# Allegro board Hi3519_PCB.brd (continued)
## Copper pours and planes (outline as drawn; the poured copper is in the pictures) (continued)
3V3 on TOP (solid shape): 78.06,32.58 78.06,30.7 79.28,29.48 79.28,28.56 79.13,28.41 77.63,28.41 77.42,28.62 77.42,32.58 77.48,32.63 78.01,32.63
3V3 on TOP (solid shape): 107.6,26.18 107.6,13.71 107.5,13.6 104.4,13.6 104.17,13.83 104.17,17.79 104.74,18.37 104.74,26.24 104.93,26.43 107.35,26.43
3V3 on TOP (solid shape): 93.27,27.7 93.27,24.3 93.48,24.09 93.48,22.04 93.45,22.01 93.17,22.01 93.12,22.06 93.12,23.81 92.77,24.17 91.37,24.17 91.22,24.32 91.22,27.65 91.45,27.88 93.1,27.88
3V3 on TOP (solid shape): 64.04,77.61 64.04,74.18 63.78,73.93 63.3,73.93 63.28,73.93 63.02,73.67 63.02,72.66 63.02,71.82 63,71.8 62.79,71.8 62.77,71.82 62.77,72.4 62.64,72.53 62.26,72.53 62.13,72.66 62.13,73.04 62.77,73.04 62.77,73.29 62.51,73.29 62.51,73.04 62.13,73.04 62.13,73.55 62.77,73.55 62.77,73.8 62.51,73.8 62.51,73.55 62.13,73.55 62.13,77.61 62.26,77.74 63.91,77.74
3V3 on BOTTOM (solid shape): 65.05,24.14 65.05,18.43 64.8,18.18 62.77,18.18 62.51,18.43 62.51,23.14 63.25,23.14 63.25,24.05 62.51,24.05 62.51,24.14 62.64,24.27 64.93,24.27
3V3 on BOTTOM (solid shape): 66.58,61.1 66.58,59.58 66.32,59.32 64.57,59.32 64.57,59.34 61.47,59.34 61.47,59.32 61.37,59.32 61.24,59.45 61.24,61.23 61.37,61.36 66.32,61.36
3V3 on BOTTOM (solid shape): 125.13,57.16 125.13,53.23 124.87,52.97 122.84,52.97 122.59,53.23 122.59,56.4 123.22,56.4 123.22,56.66 122.97,56.66 122.97,56.4 122.59,56.4 122.59,56.91 123.22,56.91 123.22,57.16 122.97,57.16 122.97,56.91 122.59,56.91 122.59,57.16 122.84,57.42 124.87,57.42
3V3 on BOTTOM (solid shape): 94.52,12.21 94.52,8.65 94.39,8.52 92.99,8.52 92.87,8.65 92.87,10.81 93.5,10.81 93.5,11.06 93.25,11.06 93.25,10.81 92.87,10.81 92.87,11.32 93.5,11.32 93.5,11.57 93.25,11.57 93.25,11.32 92.87,11.32 92.87,12.21 92.99,12.33 94.39,12.33
3V3 on BOTTOM (solid shape): 101.86,29.94 101.86,29.63 101.83,29.61 100.51,29.61 100.23,29.33 100.23,28.34 100.11,28.21 96.68,28.21 96.42,28.46 96.42,28.59 100.11,28.59 100.11,28.84 99.85,28.84 99.85,28.59 99.6,28.59 99.6,28.84 99.34,28.84 99.34,28.59 96.42,28.59 96.42,29.86 96.53,29.96 101.83,29.96
3V3 on BOTTOM (solid shape): 76.36,10.81 79.53,10.81 79.79,10.56 79.79,9.16 79.53,8.9 75.6,8.9 75.47,9.03 75.47,9.16 76.1,9.16 76.1,9.41 75.85,9.41 75.85,9.16 75.47,9.16 75.47,9.67 76.1,9.67 76.1,9.92 75.85,9.92 75.85,9.67 75.47,9.67 75.47,10.94 75.6,11.06 76.1,11.06
3V3 on BOTTOM (solid shape): 128.68,42.81 128.68,41.39 128.86,41.21 129.8,41.21 129.95,41.37 129.95,42.86 130,42.92 130.89,42.92 130.97,42.84 130.97,38.37 130.71,38.11 127.79,38.11 127.41,38.5 127.41,40.4 130.59,40.4 130.59,40.65 130.33,40.65 130.33,40.4 127.41,40.4 127.41,40.91 130.59,40.91 130.59,41.16 130.33,41.16 130.33,40.91 127.41,40.91 127.41,42.81 127.51,42.92 128.58,42.92
3V3 on BOTTOM (solid shape): 78.9,33.03 78.9,31 79.53,30.37 79.53,29.48 79.41,29.35 77.75,29.35 77.5,29.61 79.15,29.61 79.15,29.86 78.9,29.86 78.9,29.61 77.5,29.61 77.37,29.73 77.37,30.11 79.15,30.11 79.15,30.37 78.9,30.37 78.9,30.11 77.37,30.11 77.37,32.27 78.52,32.27 78.52,32.53 78.26,32.53 78.26,32.27 77.37,32.27 77.37,32.78 78.52,32.78 78.52,33.03 78.26,33.03 78.26,32.78 77.37,32.78 77.37,33.03 77.5,33.16 78.77,33.16
3V3 on POWER5 (solid shape): outline of 42251 points within 52.99,8.52 151.41,84.09
3V3 on TOP: 121.95,55.13 121.95,55.64 123.22,55.64 123.25,55.67 123.25,55.92 123.22,55.95 121.95,55.95 121.95,56.45 123.2,56.45 123.25,56.5 123.25,56.71 123.2,56.76 121.95,56.76 121.95,57.24 123.22,57.24 123.25,57.27 123.25,57.52 123.22,57.55 121.98,57.55 121.95,57.57 121.95,58.03 121.98,58.05 124.96,58.05 125.13,57.89 125.13,55.26 125,55.13
3V3 on TOP: 85.88,46.5 84.74,47.64 84.1,47.64 84.1,49.24 84.59,49.72 85.88,49.72 86.01,49.6 86.01,48.22 86.37,47.87 88.07,47.87 88.3,48.1 90.71,48.1 91.22,48.61 91.22,54.5 91.98,55.26 93.38,55.26 93.5,55.13 93.5,53.1 93.25,53.1 93.25,52.97 93.12,52.97 93.12,52.47 93.5,52.47 93.5,51.83 93.12,51.83 93.12,50.56 93.5,50.56 93.5,49.93 92.99,49.93 92.99,47.64 91.85,46.5
3V3 on BOTTOM: 111.28,50.92 111.13,51.07 110.93,51.07 110.67,51.32 109.28,51.32 109.25,51.35 109.25,51.65 109.28,51.68 111.46,51.68 111.82,51.32 113.19,51.32 113.44,51.07 113.44,45.86 113.19,45.61 111.54,45.61 111.28,45.86 ; 2 cut-outs
3V3 on BOTTOM: 121.44,69.86 121.19,69.61 121.19,68.72 121.06,68.59 119.28,68.59 117.68,70.2 117.68,77.15 118.69,78.16 119.63,78.16 119.66,78.12 119.66,77.03 119.69,77 119.66,76.98 119.66,76.72 119.79,76.6 120.55,76.6 120.68,76.47 120.68,75.22 120.45,75 120.43,75 120.03,74.6 120.03,73.31 120.32,73.01 120.32,71.44 120.63,71.13 122.2,71.13 122.26,71.08 122.26,69.92 122.2,69.86 ; 2 cut-outs
3V3 on BOTTOM: 126.52,64.02 126.52,66.44 126.78,66.69 129.7,66.69 129.95,66.44 129.95,59.7 129.76,59.51 128.05,59.51 127.95,59.61 127.95,62.59 ; 2 cut-outs
3V3_C on TOP (solid shape): 45.24,39.89 45.24,36.21 44.99,35.96 42.96,35.96 42.75,36.16 42.75,36.34 44.23,36.34 44.23,36.59 43.97,36.59 43.97,36.34 43.72,36.34 43.72,36.59 43.46,36.59 43.46,36.34 42.75,36.34 42.75,39.87 42.85,39.97 45.17,39.97
3V3_C on BOTTOM (solid shape): 43.83,38.77 43.83,36.07 43.71,35.96 41.43,35.96 41.33,36.06 41.33,36.44 42.63,36.44 42.63,36.74 41.33,36.74 41.33,37.25 42.63,37.25 42.63,37.56 41.33,37.56 41.33,38.04 42.63,38.04 42.63,38.34 41.33,38.34 41.33,38.78 41.43,38.88 43.72,38.88
3V3_C on ART03 (solid shape): outline of 348 points within 18.06,41.54 37.75,73.29
3V3_C on ART04 (solid shape): outline of 1892 points within 18.32,35.45 43.46,44.85
5V0 on TOP (solid shape): 133.24,35.71 133.24,28.83 133.18,28.77 129.55,28.77 129.44,28.87 129.44,29.8 129.44,29.86 129.19,30.11 127.67,30.11 127.54,30.24 127.54,35.83 127.67,35.96 133,35.96
5V0 on TOP: 151.67,45.3 151.54,45.43 148.7,45.43 148.62,45.35 148.62,44.85 148.67,44.8 151.57,44.8 151.67,44.9
5V0 on TOP: 116.92,50.69 115.68,50.69 115.47,50.89 115.47,52.26 115.65,52.44 118.75,52.44 118.78,52.42 118.78,51.98 118.75,51.96 117.48,51.96 117.43,51.91 117.43,51.7 117.48,51.65 118.7,51.65 118.78,51.58 118.78,51.22 118.7,51.15 117.53,51.15 117.52,51.13 117.37,51.13
5V0 on BOTTOM: 151.54,44.85 151.41,44.72 149.13,44.72 148.75,45.1 148.75,46.5 148.24,47 147.35,47 147.1,47.26 147.1,49.04 147.35,49.29 151.41,49.29 151.54,49.16 ; 2 cut-outs
5V0 on BOTTOM: 115.35,53.74 118.65,53.74 118.9,53.48 118.9,48.4 118.65,48.15 115.35,48.15 115.09,48.4 115.09,53.48 ; 4 cut-outs
5V0 on ART04: 151.54,50.18 151.54,43.96 151.29,43.7 134.78,43.7 133.38,42.31 133.38,42.28 133.25,42.15 133.25,33.29 133,33.03 126.52,33.03 126.14,33.42 126.14,42.81 121.82,47.13 116.36,47.13 115.35,48.15 115.35,52.34 116.74,53.74 130.51,53.74 133.37,50.88 139.39,50.88 139.68,50.59 151.14,50.59
5V0_C on TOP (solid shape): 28.61,37.1 28.61,29.83 28.49,29.72 27.02,29.72 26.85,29.89 26.85,37.12 26.95,37.23 28.48,37.23
5V0_C on TOP (solid shape): 26.45,53.35 26.45,47.51 26.32,47.39 25.3,47.39 25.23,47.46 25.23,51.02 24.67,51.58 24.67,53.35 24.8,53.48 26.32,53.48
5V0_C on TOP (solid shape): 47.4,45.1 47.4,41.42 47.27,41.29 44.86,41.29 44.73,41.42 44.73,41.67 46.26,41.67 46.26,41.92 46,41.92 46,41.67 45.75,41.67 45.75,41.92 45.5,41.92 45.5,41.67 44.73,41.67 44.73,45.1 44.86,45.23 47.27,45.23
5V0_C on BOTTOM (solid shape): 47.4,42.76 47.4,41.62 47.29,41.51 46.68,41.51 46.64,41.54 45.19,41.54 45.14,41.59 45.14,42.03 45.17,42.05 46.61,42.05 46.64,42.08 46.64,42.28 46.56,42.36 45.22,42.36 45.14,42.43 45.14,42.76 45.22,42.84 47.33,42.84
5V0_C on POWER5 (solid shape): outline of 2607 points within 25.16,35.63 47.15,51.58
5V_AUDIO on TOP (solid shape): 22.99,60.97 22.99,59.45 23.02,59.43 23.27,59.43 23.3,59.45 23.3,60.97 23.32,61 23.63,61 23.65,60.97 23.65,58.89 22.92,58.89 22.92,56.96 23.65,56.96 23.65,56.66 23.91,56.4 26.19,56.4 26.32,56.28 26.32,54.29 26.19,54.17 24.57,54.17 20.68,54.17 20.48,54.37 20.48,58.78 20.8,59.1 22.41,59.1 22.61,59.3 22.61,60.97 22.64,61 22.97,61
5V_C_AUDIO on TOP (solid shape): 24.24,35.7 26.19,35.7 26.45,35.45 26.45,33.67 26.03,33.25 26.03,29.95 25.79,29.71 22.43,29.71 22.13,30.01 22.13,34.94 21.85,35.22 21.21,35.22 20.93,34.94 20.93,33.47 20.88,33.42 20.63,33.42 20.58,33.47 20.58,35.42 21.24,36.08 21.24,36.34 23.14,36.34 23.14,36.59 22.89,36.59 22.89,36.34 22.64,36.34 22.64,36.59 22.38,36.59 22.38,36.34 22,36.34 22,36.59 21.75,36.59 21.75,36.34 21.24,36.34 21.24,36.84 21.37,36.97 22.97,36.97
5V_USB2.0 on TOP (solid shape): 23.78,48.78 23.78,47.39 22.62,47.39 22.47,47.24 22.47,44.21 22.28,44.02 15.71,44.02 13.72,46.01 21.21,46.01 21.22,45.96 21.23,45.9 21.25,45.85 21.27,45.8 21.31,45.75 21.35,45.71 21.39,45.68 21.44,45.65 21.49,45.63 21.55,45.61 21.61,45.61 21.66,45.61 21.72,45.62 21.77,45.64 21.82,45.66 21.87,45.69 21.91,45.73 21.95,45.77 21.98,45.82 22,45.87 22.02,45.93 22.03,45.99 22.03,46.04 22.02,46.1 22,46.15 21.98,46.21 21.95,46.25 21.91,46.3 21.87,46.34 21.82,46.37 21.77,46.39 21.72,46.41 21.66,46.42 21.61,46.42 21.55,46.42 21.49,46.4 21.44,46.38 21.39,46.35 21.35,46.32 21.31,46.28 21.27,46.23 21.25,46.18 21.23,46.13 21.22,46.07 21.21,46.01 13.72,46.01 13.62,46.12 13.62,48.27 23.65,48.27 23.65,48.53 23.4,48.53 23.4,48.27 23.14,48.27 23.14,48.53 22.89,48.53 22.89,48.27 13.62,48.27 13.62,48.66 13.87,48.91 23.65,48.91
5V_USB2.0 on ART03 (solid shape): outline of 192 points within 3.71,38.88 15.65,49.16
12V0 on TOP: 128.81,14.24 126.46,16.59 115.11,16.59 114.97,16.73 114.97,17.92 114.84,18.05 114.58,18.05 114.2,18.43 112.88,18.43 112.37,17.92 112.37,16.37 112.35,16.35 112.07,16.35 112.04,16.37 112.04,18.2 112.68,18.84 112.68,20.06 112.88,20.26 127.59,20.26 128.55,21.22 128.55,22.24 128.4,22.39 127.03,22.39 126.98,22.44 126.98,22.72 127.01,22.75 132.31,22.75 132.36,22.7 132.36,18.94 132.81,18.49 148.56,18.49 148.95,18.1 148.95,14.54 148.64,14.24
AGND on TOP (solid shape): outline of 6086 points within 0.67,7.51 48.75,86.48
AGND on BOTTOM (solid shape): outline of 6561 points within 0.67,7.51 48.75,86.48
AGND on GND02 (solid shape): outline of 6784 points within 0.67,7.51 48.75,86.48
AGND on ART03 (solid shape): outline of 5767 points within 0.67,7.51 48.75,86.48
AGND on ART04 (solid shape): outline of 6110 points within 0.67,7.51 48.75,86.48
AGND on POWER5 (solid shape): outline of 6389 points within 0.67,7.51 48.75,86.48
AVDD_1.05V on BOTTOM: 121.82,76.09 121.7,76.21 121.7,77.23 121.82,77.36 122.59,77.36 122.84,77.1 123.73,77.1 123.98,77.36 126.52,77.36 127.79,76.09 129.19,76.09 129.44,75.83 129.44,71.77 129.32,71.64 127.28,71.64 127.16,71.77 127.16,72.4 127.28,72.53 127.92,72.53 128.05,72.66 128.05,74.69 127.79,74.94 126.65,74.94 125.51,76.09 ; 6 cut-outs
AVDD_3V3_PHY on ART04 (solid shape): 126.27,76.91 126.27,74.06 126.65,73.67 127.16,73.67 127.28,73.55 127.28,72.79 127.03,72.53 125.63,72.53 125.1,73.07 125.1,74.84 122.86,77.09 124.15,77.09 124.15,77.03 124.16,76.97 124.18,76.92 124.21,76.87 124.24,76.82 124.28,76.78 124.32,76.74 124.37,76.71 124.42,76.69 124.47,76.67 124.53,76.66 124.59,76.66 124.64,76.67 124.7,76.69 124.75,76.71 124.8,76.74 124.84,76.78 124.88,76.82 124.91,76.87 124.94,76.92 124.96,76.97 124.96,77.03 124.97,77.09 124.96,77.14 124.95,77.2 124.93,77.25 124.9,77.3 124.86,77.34 124.82,77.38 124.78,77.42 124.73,77.44 124.67,77.46 124.62,77.48 124.56,77.48 124.5,77.48 124.45,77.46 124.39,77.44 124.34,77.42 124.3,77.38 124.26,77.34 124.22,77.3 124.19,77.25 124.17,77.2 124.16,77.14 124.15,77.09 122.86,77.09 122.84,77.1 122.84,77.78 123.86,78.79 124.39,78.79
AVDD_3V3_PHY on BOTTOM: 123.47,77.36 123.09,77.36 122.84,77.61 121.7,77.61 121.44,77.36 121.44,76.98 121.32,76.85 120.43,76.85 120.3,76.98 120.3,78.63 120.43,78.75 125.13,78.75 125.25,78.63 125.25,77.74 125.13,77.61 123.73,77.61
DDRIO_1.5V/1.35V on TOP (solid shape): 66.83,71.13 66.83,63.51 66.58,63.26 64.04,63.26 63.78,63.51 63.78,71.01 64.65,71.01 64.9,71.26 66.71,71.26
DDRIO_1.5V/1.35V on BOTTOM (solid shape): 86.09,54.75 86.09,54.52 85.6,54.04 85.6,53.58 85.27,53.25 84.94,53.25 84.84,53.15 84.41,53.15 84.31,53.25 84.31,53.86 84.31,53.99 85.37,53.99 85.37,54.24 84.99,54.24 84.99,53.99 84.31,53.99 84.31,54.17 84.1,54.37 83.42,54.37 83.36,54.43 83.36,54.86 83.44,54.94 85.9,54.94
DDRIO_1.5V/1.35V on TOP: 89.57,55.01 89.57,53.71 89.13,53.28 88.75,53.28 88.7,53.23 85.65,53.23 85.27,52.85 84.23,52.85 84.1,52.97 84.1,55.01 84.23,55.13 85.76,55.13 85.88,55.01 85.88,54.5 86.01,54.37 88.55,54.37 88.68,54.5 88.68,55.01 88.8,55.13 89.44,55.13
DDRIO_1.5V/1.35V on POWER5: 78.06,52.92 77.66,52.92 67.7,62.88 65.29,62.88 64.93,63.24 64.93,70.52 69.86,75.45 84.13,75.45 89.82,69.76 89.82,58.92 90.07,58.66 90.07,57.11 89.95,56.99 89.95,54.93 89,53.99 85.32,53.99 84.99,53.66 84.99,52.52 84.43,51.96 79.02,51.96
DVDD_1.05V on BOTTOM: 121.7,69.61 128.55,69.61 128.68,69.48 128.68,68.47 128.55,68.34 121.7,68.34 121.57,68.47 121.57,69.48 ; 3 cut-outs
GND on ART03 (solid shape): 59.88,33.45 70.91,33.45 71.02,33.39 71.02,33.26 71.38,32.67 71.74,33.26 71.74,33.39 71.85,33.45 71.95,33.45 72.06,33.39 72.06,33.26 72.42,32.67 72.78,33.26 72.78,33.39 72.89,33.45 82.53,33.45 82.57,33.49 82.67,33.49 82.73,33.45 82.72,33.38 81.6,32.26 69.4,32.26 69.29,32.34 69.31,32.48 69.02,33.16 68.72,32.48 68.75,32.34 68.63,32.26 60.71,32.26 59.69,33.28 59.67,33.41 59.78,33.49 59.84,33.49
GND on ART03 (solid shape): outline of 13313 points within 51.77,7.51 163.57,86.48
GND on ART04 (solid shape): outline of 19799 points within 51.77,7.51 163.57,86.48
GND on POWER5 (solid shape): outline of 3585 points within 51.77,7.51 163.57,86.48
GND on TOP: 54.31,7.51 52.51,8.25 51.77,10.05 51.77,83.94 52.51,85.74 54.31,86.48 161.03,86.48 162.82,85.74 163.57,83.94 163.57,10.05 162.82,8.25 161.03,7.51 ; 118 cut-outs
GND on TOP: 138.97,54.62 138.71,54.88 131.22,54.88 130.84,54.5 130.84,47.64 131.09,47.39 138.71,47.39 138.97,47.64
GND on TOP: 87.99,48.36 87.99,48.43 87.93,48.49 88.14,49.04 87.55,49.04 87.49,49.04 87.2,49.2 86.9,49.04 86.7,49.04 86.64,49.09 86.64,49.62 86.19,50.08 85.43,50.08 85.2,50.31 85.2,52.11 85.36,52.28 86.28,52.28 86.66,51.78 86.64,52.41 86.82,52.59 89.49,52.59 89.64,52.44 89.64,52.34 90.07,51.91 90.18,51.91 90.33,51.75 90.4,51.75 90.71,51.45 90.71,51.42 91.14,50.99 91.14,48.95 90.56,48.36 90.43,48.36 90.43,48.81 90.25,48.99 89.39,48.99 89.29,49.09 89.26,49.09 89.21,49.04 89.21,48.96 89.16,48.91 89.16,48.36 ; 1 cut-out
GND on TOP: 125.38,75.45 125.38,71.26 125.25,71.13 121.19,71.13 120.93,71.39 120.93,75.45 121.06,75.58 125.25,75.58
GND on BOTTOM: 130.97,48.53 130.97,52.72 132.24,53.99 138.97,53.99 139.35,53.61 139.35,48.53 139.1,48.27 131.22,48.27 ; 12 cut-outs
GND on BOTTOM: 120.93,75.83 121.06,75.96 121.57,75.96 121.7,75.83 125.38,75.83 125.76,75.45 125.76,74.56 125.25,74.06 125.25,71.52 125.13,71.39 121.06,71.39 120.58,71.87 120.58,73.17 120.38,73.37 120.38,74.51 120.93,75.07 ; 6 cut-outs
GND on BOTTOM: 54.31,7.51 52.51,8.25 51.77,10.05 51.77,83.94 52.51,85.74 54.31,86.48 161.03,86.48 162.82,85.74 163.57,83.94 163.57,10.05 162.82,8.25 161.03,7.51 ; 144 cut-outs
GND on GND02: 54.81,7.51 54.31,7.51 52.51,8.25 51.77,10.05 51.77,10.56 51.77,83.86 51.77,83.94 52.51,85.74 54.31,86.48 160.79,86.48 161.03,86.48 162.82,85.74 163.57,83.94 163.57,59.32 163.57,10.56 163.57,10.05 162.82,8.25 161.03,7.51 160.52,7.51 ; 3 cut-outs
GND on ART03: 109,67.96 108.74,67.71 105.57,67.71 105.19,68.09 105.19,77.61 105.69,78.12 108.36,78.12 109,77.48
VDDREG_3.3V on BOTTOM: 126.4,73.17 126.4,69.99 126.27,69.86 122.97,69.86 122.92,69.92 122.92,71.06 122.99,71.13 125.38,71.13 125.51,71.26 125.51,73.93 126.27,74.69 126.9,74.69 127.03,74.56 127.03,73.8 ; 2 cut-outs
(no net) on TOP: 127.54,30.24 127.54,35.83 127.67,35.96 133,35.96 133.24,35.71 133.24,28.83 133.18,28.77 129.55,28.77 129.44,28.87 129.44,29.86 129.19,30.11 127.67,30.11
IO3V3_SII9022A on BOTTOM: 127.98,58.63 128.17,58.82 142.91,58.82 143.29,58.43 143.29,56.78 143.03,56.53 131.48,56.53 129.44,54.5 128.17,54.5 127.98,54.69 ; 3 cut-outs
IRIS_5V0 on BOTTOM (solid shape): outline of 90 points within 79.02,54.75 117.89,81.04
Net_162 on TOP (solid shape): 77.27,8.97 74.22,8.97 74.22,10.11 77.27,10.11
Net_163 on TOP (solid shape): 90.8,8.97 87.75,8.97 87.75,10.11 90.8,10.11
Net_164 on BOTTOM (solid shape): 155.21,65.78 153.94,65.78 153.94,67.1 155.21,67.1
Net_165 on BOTTOM (solid shape): 156.99,65.78 155.72,65.78 155.72,68.11 156.99,68.11
Net_166 on BOTTOM (solid shape): 155.21,75.94 153.94,75.94 153.94,78.27 155.21,78.27
Net_167 on BOTTOM (solid shape): 156.99,76.95 155.72,76.95 155.72,78.27 156.99,78.27
REG_OUT_1.05V on BOTTOM: 129.44,70.5 129.44,68.47 129.57,68.34 132.36,68.34 132.62,68.59 132.62,78.88 132.24,79.26 130.21,79.26 129.95,79.01 129.95,76.98 130.08,76.85 130.08,73.55 130.59,73.04 130.59,71.64 ; 2 cut-outs
SDIO0_VDD_3.3V on BOTTOM: 147.02,31.89 140.37,31.89 140.24,32.02 140.24,32.78 140.37,32.91 148.49,32.91 148.75,32.65 150.42,32.65 150.47,32.6 150.47,31.94 150.46,31.93 147.06,31.93 ; 4 cut-outs
SDIO1_VDD_3.3V on TOP: 150.35,30.55 150.4,30.49 150.4,29.89 150.35,29.83 148.72,29.83 147.86,28.97 140.67,28.97 140.57,29.07 140.57,30.44 140.67,30.55 ; 4 cut-outs
$5N49 on TOP (solid shape): 112.13,26.34 112.13,18.95 111.74,18.56 111.74,17.92 111.73,17.92 111.73,16.39 111.69,16.35 111.41,16.35 111.38,16.37 111.38,17.82 111.26,17.95 110.39,17.95 109.38,18.96 109.38,26.3 109.5,26.43 112.04,26.43
$5N87 on TOP: 133.25,24.04 133.25,26.66 133.1,26.81 129.62,26.81 129.44,26.63 129.44,25.54 129.29,25.39 128.71,25.39 128.61,25.29 128.61,23.66 128.35,23.41 127.01,23.41 126.98,23.38 126.98,23.08 127.01,23.05 132.26,23.05
$5N129 on TOP (solid shape): 153.19,15.38 153.19,10.81 152.68,10.3 145.46,10.3 145.33,10.43 145.33,12.87 145.44,12.97 149.26,12.97 149.51,13.22 149.51,15.38 149.76,15.64 152.94,15.64
$6N32 on TOP (solid shape): 66.83,73.47 66.83,72.35 66.76,72.28 64.55,72.28 64.29,72.53 63.59,72.53 63.53,72.48 63.53,71.82 63.51,71.8 63.3,71.8 63.28,71.82 63.28,73.45 63.42,73.59 66.72,73.59
$6N85 on BOTTOM: 97.16,31.64 100.23,31.64 100.36,31.51 100.36,30.72 100.46,30.62 101.83,30.62 101.86,30.6 101.86,30.32 101.81,30.27 97.19,30.27 97.08,30.37 97.08,31.56
$7N68 on BOTTOM: 111.92,51.7 111.64,51.98 109.28,51.98 109.25,52.01 109.25,52.31 109.28,52.34 110.77,52.34 111.28,52.85 114.05,52.85 114.2,52.69 114.2,51.83 114.08,51.7
$7N137 on BOTTOM: 105.69,52.85 106.1,52.44 106.58,52.44 106.69,52.34 107.9,52.34 107.96,52.29 107.96,52.01 107.93,51.98 106.33,51.98 106.05,51.7 103.33,51.7 103.28,51.75 103.28,52.8 103.33,52.85
$8N21 on TOP (solid shape): 94.14,20.69 94.14,19.19 94.65,18.68 94.65,16.27 94.52,16.14 93.63,16.14 93.5,16.27 93.5,18.43 93.76,18.68 93.76,20.69 93.78,20.72 94.11,20.72
$8N46 on TOP (solid shape): 94.77,26.23 94.77,24.02 94.14,23.38 94.14,22.04 94.11,22.01 93.81,22.01 93.78,22.04 93.78,24.17 93.63,24.32 93.63,26.25 93.65,26.28 94.72,26.28
$16N153 on TOP: 125.89,75.45 129.19,75.45 129.32,75.58 129.32,77.23 129.19,77.36 125.89,77.36 125.76,77.23 125.76,75.58
$16N153 on BOTTOM: 129.32,76.34 128.05,76.34 127.79,76.6 127.79,79.01 127.92,79.14 128.88,79.14 128.96,79.06 128.96,77.38 129.44,76.9 129.44,76.47
$16N321 on BOTTOM (solid shape): 135.16,76.85 135.16,67.32 135.03,67.2 134.02,67.2 133.89,67.32 133.89,76.09 134.78,76.09 134.78,76.34 134.52,76.34 134.52,76.09 133.89,76.09 133.89,76.6 134.78,76.6 134.78,76.85 134.52,76.85 134.52,76.6 133.89,76.6 133.89,76.85 134.02,76.98 135.03,76.98
$16N362 on BOTTOM: 140.24,77.94 140.24,74.56 140.37,74.44 141.13,74.44 141.25,74.56 141.25,76.09 141.51,76.34 141.51,77.97 141.43,78.04 140.34,78.04
$16N468 on BOTTOM: 146.72,76.72 146.46,76.98 143.79,76.98 142.21,75.39 142.21,75.38 142.04,75.21 142.04,73.07 141.89,72.91 141.89,67.96 142.78,67.07 146.46,67.07 146.72,67.32
$22N94 on TOP (solid shape): 56.42,55.89 56.42,54.37 56.29,54.24 54.51,54.24 54.26,54.5 54.26,55.89 54.39,56.02 56.29,56.02
$22N94 on BOTTOM (solid shape): 61.47,58.54 64.44,58.54 64.55,58.43 64.55,57.04 64.42,56.91 58.58,56.91 58.07,56.4 58.07,54.24 57.94,54.12 54.51,54.12 54.26,54.37 54.26,57.93 57.31,57.93 57.31,58.18 57.05,58.18 57.05,57.93 56.8,57.93 56.8,58.18 56.55,58.18 56.55,57.93 54.26,57.93 54.26,58.05 54.77,58.56 61.47,58.56
$28N1296 on TOP (solid shape): 33.58,76.34 33.58,73.34 33.53,73.29 24.54,73.29 24.16,73.67 24.16,76.75 24.22,76.81 33.11,76.81

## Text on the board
BOTTOM: HI3519DMEB VER.A  ARTWORK LAYER06
Ref Des/Silkscreen Bottom: E | HI3519DMEB VER.A  SILKSCREEN BOTTOM | BAR CODE
User.Comments: HI3519DMEB VER.A  SOLDMASK TOP | HI3519DMEB VER.A  SOLDMASK BOTTOM
TOP: HI3519DMEB VER.A ARTWORK LAYER01
Ref Des/Silkscreen Top: USB_2.0 | RS485+FLASH TRIG | SHUTTER TRIG | AUDIO MIC OUT | AUDIO MIC IN | CVBS | AUDIO_OUT_AMP | D | E | DIF MIC IN1 | DIF MIC IN2 | MIC_IN | P-IRIS | AI CONTROL | SFC_EMMC_DEVICE_MODE | 0 (Default) | 0 | 1 | 1(DEFAULT) | 0 (DEFAULT) | SW1.2 | SW2.3 | 0 0 (Default) | BOOT_SEL[1:0] | SFC_DEVICE_MODE | SPI NOR FLASH | SPI NAND FLASH | UPDATE_FROM_SDIO0 | DISABLE | ENABLE | 0 0 | 1 0 | JTAG | UART | 3 BYTE ADDRESS MODE | 1 I/O MODE | 4 BYTE ADDRESS MODE | 4 I/O MODE | 8 I/O MODE | SW1.3 | ADC0 | SW1.4 | SPI FLASH | NAND FLASH | B | EMMC | PCIE | SW2.1 | SW2.2 | SW2.4 | 0:RGMII | 0:DISABLE JTAG | 0:DISABLE | 0:FLASH OR PCIE | 1:VO | 1:ENABLE JTAG | 1:ENABLE | 1:BOOTROM | SD_CARD | ETH_RJ45 | POWER_IN | HDMI | DF_MIC_IN | CLK_TEST | HI3519DMEB VER.A | HI3519DMEB VER.A  SILKSCREEN TOP | www.NTpcb.com
GND02: HI3519DMEB VER.A  ARTWORK LAYER02
ART03: HI3519DMEB VER.A  ARTWORK LAYER03
ART04: HI3519DMEB VER.A  ARTWORK LAYER04
POWER5: HI3519DMEB VER.A  ARTWORK LAYER05
DIMENSION: 100 ohm | 90 ohm | 3 | 4 | 4/8 | 4.5/6.5 | + | - | 10% | Default | 1--ART01 | 2--GROUND PLANE02 | 3--ART03 | 4--ART04 | 5--POWER PLANE05 | 6--ART06
DISPLAY_BOTTOM: HI3519DMEB VER.A  PASTEMASK BOTTOM
DISPLAY_TOP: HI3519DMEB VER.A  PASTEMASK TOP
